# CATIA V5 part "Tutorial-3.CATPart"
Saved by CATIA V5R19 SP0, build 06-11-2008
Part number: Part1
Bounding box of the stored display mesh (mm): x -75 to 75, y -40 to 40, z 0 to 5
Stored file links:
  D:\Shriniwas\v5_r19\Part files\C15\TUT3.CATPart
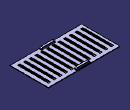
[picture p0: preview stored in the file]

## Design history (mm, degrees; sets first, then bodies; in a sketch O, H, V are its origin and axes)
SheetMetalParameters1: BendRadius 2, ReliefAxialLength 2, ReliefRadialLength 1, MinimumBendRadius 0, Thickness 1, KFactor 0.400515 {= log(min(100,max(20*SheetMetalParameters1.BendRadius,SheetMetalParameters1.Thickness)/SheetMetalParameters1.Thickness))/log(100)/2}
Body1 (main body)
  Sketch1 on xy-plane, origin (0, 0, 0), H (1, 0, 0), V (0, 1, 0)
    line L1 (75, 40) -> (75, -40)
    line L2 (75, -40) -> (-75, -40)
    line L3 (-75, -40) -> (-75, 40)
    line L4 (-75, 40) -> (75, 40)
    length L4 = 150
    length L1 = 80
    vertical: L1 V, L3 V
    horizontal: L2 H, L4 H
    equidistance: L1 L3 O, L2 L4 O
  Wall1: Thickness 1, Profile Sketch1
  Sketch2 on face of Wall1, origin (0, 0, 0), H (1, 0, 0), V (0, 1, 0)
    line L1 (64.5, 30) -> (67, 30)
    line L2 (67, 30) -> (67, -30)
    line L3 (67, -30) -> (64.5, -30)
    line L4 (64.5, -30) -> (64.5, 30)
    reference projected line E1 (75, 40) -> (75, -40) from edge [face of Wall1 | face of Wall1]
    reference projected line E2 (-75, 40) -> (75, 40) from edge [face of Wall1 | face of Wall1]
    length L2 = 60
    distance L2 L4 = 2.5
    distance E1 L2 = 8
    distance L1 E2 = 10
    horizontal: L1 H, L3 H
    vertical: L2 V, L4 V
  d_Stamp1: Stamp_FilletRadius 2, NewRoot_AttribNormalisation "No Standard"
  RectPattern1: of d_Stamp1, direction 1 instances 12, spacing 12, along face of Wall1 reversed
  Sketch3 on face of Wall1, origin (0, 0, 0), H (1, 0, 0), V (0, -1, 0)
    point P1 (0, 36.5)
    reference projected line E1 (75, 40) -> (75, -40) from edge [face of Wall1 | face of Wall1]
    reference projected line E2 (-75, 40) -> (75, 40) from edge [face of Wall1 | face of Wall1]
    distance P1 E1 = 75
    distance P1 E2 = 3.5
  Sketch4 on face of Wall1, origin (0, -36.5, 0), H (1, 0, 0), V (0, 1, 0)
    point P1 (0, 0)
    reference projected point E1 (0, 0) from Sketch3.P1
    coincidence: E1 P1
  d_Stamp2: Stamp_FilletRadius 0.5, NewRoot_AttribNormalisation "No Standard"
  SHM_Mirror1: MirroringPlane zx-plane, ObjectToMirror d_Stamp2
